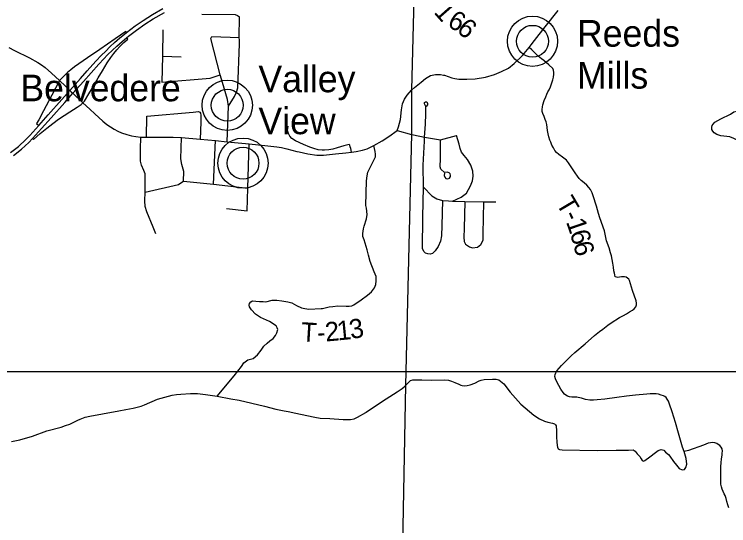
# Model space of a CAD drawing. Extents: x 2402298 to 2498138, y 789485 to 950881.
# Drawn here: x 2448638 to 2459820, y 856862 to 864863 of the extents above; entities that cross this region are included whole.
import ezdxf

# ---------------------------------------------------------------- set-up
doc = ezdxf.new("R2010")
doc.units = 0
for name, color, linetype in [('GM_X_County_Road', 7, 'Continuous'), ('GM_X_Interchange_Ramps', 7, 'Continuous'), ('GM_X_Township', 7, 'Continuous'), ('GM_X_Township_Road', 7, 'Continuous'), ('GM_X_Township_Road_Text', 7, 'Continuous'), ('GM_X_Unincorporated', 7, 'Continuous'), ('GM_X_Unincorporated_Text', 7, 'Continuous'), ('GM_X_US_Route', 7, 'Continuous'), ('SH_Text', 7, 'Continuous')]:
    doc.layers.add(name, color=color, linetype=linetype)

msp = doc.modelspace()

# ---------------------------------------------------------------- linework, layer by layer
at = {"layer": 'GM_X_County_Road'}
msp.add_line((2456697, 864345), (2456728, 864386), dxfattribs=at)
for points in [[(2456728, 864386), (2456778, 864452), (2456948, 864667), (2457153, 864924)], [(2448552, 864344), (2448641, 864299), (2448876, 864182), (2449005, 864111), (2449066, 864071), (2449119, 864030), (2449219, 863942), (2449346, 863825), (2449440, 863736), (2449509, 863672), (2449531, 863651)], [(2455372, 863908), (2455486, 863871), (2455535, 863856), (2455598, 863849), (2455720, 863848), (2455853, 863855), (2456015, 863878), (2456152, 863919), (2456262, 863966), (2456372, 864019), (2456464, 864093), (2456590, 864218), (2456697, 864345)], [(2453060, 862718), (2453095, 862709), (2453235, 862678), (2453372, 862660), (2453477, 862661), (2453574, 862667), (2453663, 862678), (2453827, 862695), (2453918, 862706), (2453987, 862714), (2454087, 862735), (2454159, 862758), (2454268, 862810), (2454394, 862884), (2454502, 862949), (2454631, 863047), (2454653, 863100), (2454682, 863219), (2454700, 863369), (2454716, 863462), (2454746, 863537), (2454785, 863598), (2454854, 863676), (2454900, 863715), (2455006, 863803), (2455074, 863860), (2455153, 863905), (2455230, 863922), (2455307, 863923), (2455356, 863913), (2455372, 863908)], [(2449531, 863651), (2449557, 863627), (2449712, 863480), (2449823, 863378), (2449901, 863305), (2450023, 863193), (2450087, 863140), (2450144, 863100), (2450201, 863066), (2450260, 863034), (2450318, 863008), (2450399, 862980), (2450474, 862961), (2450541, 862950), (2450619, 862940), (2450708, 862940), (2450982, 862943), (2451125, 862942), (2451251, 862935)], [(2451251, 862935), (2451256, 862935), (2451550, 862909), (2451785, 862886), (2451969, 862869), (2452314, 862838), (2452605, 862807), (2452745, 862791), (2452820, 862778), (2452902, 862758), (2453060, 862718)]]:
    msp.add_lwpolyline(points, dxfattribs=at)
at = {"layer": 'GM_X_Interchange_Ramps'}
for points in [[(2450392, 864576), (2450382, 864592), (2450218, 864480), (2449977, 864311), (2449785, 864180), (2449647, 864086), (2449580, 864039), (2449524, 863996), (2449473, 863953), (2449424, 863907), (2449362, 863845), (2449346, 863825)], [(2449712, 863480), (2449739, 863506), (2449805, 863618), (2449860, 863710), (2449953, 863867), (2450019, 863979), (2450094, 864105), (2450147, 864186), (2450194, 864250), (2450242, 864308), (2450290, 864359), (2450354, 864422), (2450415, 864476), (2450400, 864499)], [(2449346, 863825), (2449328, 863795), (2449282, 863707), (2449225, 863598), (2449137, 863429), (2449096, 863350), (2449021, 863210), (2448987, 863156), (2449021, 863122)], [(2448925, 862921), (2448939, 862906), (2449045, 863000), (2449147, 863084), (2449243, 863157), (2449331, 863221), (2449507, 863336), (2449623, 863412), (2449685, 863450), (2449712, 863480)]]:
    msp.add_lwpolyline(points, dxfattribs=at)
at = {"layer": 'GM_X_Township'}
msp.add_lwpolyline([(2436952, 871501), (2441170, 871455), (2443539, 871409), (2448340, 871349), (2451564, 871308), (2453075, 871274), (2455047, 871253), (2454976, 868366), (2454948, 867221), (2454912, 865985), (2454911, 865959), (2454910, 865921), (2454853, 863679), (2454854, 862987), (2454763, 859062), (2454590, 849912), (2454510, 846829), (2454470, 845007), (2454435, 843954)], dxfattribs=at)
at = {"layer": 'GM_X_Township_Road'}
for p, q in [((2451729, 864513), (2452160, 864498)), ((2456697, 864345), (2456728, 864386)), ((2450956, 864207), (2451249, 864198)), ((2451757, 862207), (2451785, 862886))]:
    msp.add_line(p, q, dxfattribs=at)
for points in [[(2456728, 864386), (2456778, 864452), (2456948, 864667), (2457153, 864924)], [(2451575, 864863), (2452096, 864857), (2452133, 864844), (2452162, 864821)], [(2452162, 864456), (2452160, 864498), (2452162, 864821)], [(2450962, 864621), (2450956, 864207), (2450949, 863803), (2451702, 863863), (2451863, 863914)], [(2451989, 863423), (2451975, 863532), (2451914, 863743), (2451863, 863914), (2451716, 864482), (2451729, 864513)], [(2451969, 862869), (2451989, 863423), (2452085, 863577), (2452117, 863643), (2452138, 863710), (2452164, 864399), (2452162, 864456)], [(2459823, 857140), (2459804, 857188), (2459788, 857240), (2459778, 857286), (2459764, 857333), (2459750, 857363), (2459733, 857399), (2459718, 857434), (2459707, 857472), (2459699, 857511), (2459695, 857564), (2459694, 857624), (2459695, 857681), (2459694, 857740), (2459695, 857789), (2459701, 857847), (2459708, 857910), (2459715, 857964), (2459718, 857998), (2459720, 858027), (2459717, 858063), (2459703, 858090), (2459683, 858116), (2459656, 858134), (2459633, 858149), (2459605, 858160), (2459571, 858164), (2459537, 858161), (2459500, 858151), (2459424, 858123), (2459350, 858094), (2459263, 858065), (2459189, 858041), (2459125, 858024), (2459098, 858090), (2459036, 858311), (2458987, 858479), (2458935, 858644), (2458895, 858764), (2458876, 858811), (2458859, 858841), (2458839, 858866), (2458822, 858883), (2458799, 858895), (2458761, 858907), (2458719, 858918), (2458683, 858923), (2458645, 858926), (2458592, 858923), (2458538, 858919), (2458362, 858902), (2458220, 858887), (2458071, 858867), (2457883, 858844), (2457759, 858829), (2457703, 858825), (2457645, 858828), (2457578, 858838), (2457518, 858855), (2457466, 858867), (2457441, 858871), (2457403, 858871), (2457364, 858872), (2457326, 858879), (2457298, 858888), (2457272, 858904), (2457251, 858922), (2457227, 858947), (2457192, 858996), (2457162, 859054), (2457124, 859121), (2457107, 859162), (2457101, 859197), (2457104, 859229), (2457114, 859255), (2457132, 859285), (2457166, 859325), (2457205, 859367), (2457265, 859432), (2457352, 859518), (2457413, 859570), (2457571, 859705), (2457720, 859836), (2457799, 859901), (2457848, 859939), (2457928, 860001), (2457979, 860037), (2458111, 860118), (2458173, 860152), (2458220, 860178), (2458268, 860206), (2458312, 860235), (2458338, 860257), (2458364, 860288), (2458376, 860317), (2458376, 860342), (2458373, 860379), (2458316, 860544), (2458267, 860697), (2458256, 860717), (2458235, 860736), (2458216, 860748), (2458190, 860755), (2458164, 860758), (2458140, 860756), (2458108, 860750), (2458083, 860747), (2458061, 860748), (2458044, 860758), (2458035, 860786), (2458030, 860812), (2458023, 860851), (2458016, 860905), (2458007, 860968), (2457986, 861082), (2457972, 861131), (2457949, 861211), (2457909, 861320), (2457874, 861473), (2457804, 861678), (2457781, 861747), (2457750, 861863), (2457699, 862023), (2457683, 862072), (2457657, 862121), (2457633, 862154), (2457601, 862190), (2457560, 862226), (2457509, 862265), (2457477, 862296), (2457453, 862329), (2457417, 862385), (2457311, 862540), (2457280, 862580), (2457221, 862629), (2457162, 862670), (2457127, 862703), (2457100, 862732), (2457075, 862774), (2457054, 862818), (2457038, 862860), (2457021, 862896), (2457006, 862944), (2456993, 862992), (2456985, 863047), (2456978, 863091), (2456972, 863137), (2456963, 863182), (2456949, 863219), (2456932, 863262), (2456911, 863309), (2456900, 863342), (2456898, 863373), (2456903, 863413), (2456910, 863447), (2456930, 863512), (2456955, 863574), (2456971, 863613), (2456991, 863649), (2457009, 863682), (2457029, 863726), (2457055, 863804), (2457065, 863838), (2457077, 863880), (2457084, 863925), (2457083, 863953), (2457077, 863990), (2457068, 864013), (2457007, 864072), (2456925, 864140), (2456892, 864166), (2456840, 864208), (2456789, 864257), (2456736, 864305), (2456697, 864345)], [(2455057, 862880), (2455060, 862942), (2455074, 863144), (2455080, 863305), (2455081, 863420), (2455068, 863440), (2455061, 863464), (2455061, 863481), (2455075, 863495), (2455094, 863493), (2455102, 863483), (2455106, 863467), (2455103, 863448), (2455087, 863420)], [(2450708, 862940), (2450713, 863270), (2451440, 863333), (2451520, 863344), (2451540, 863334), (2451555, 863316), (2451559, 863283), (2451556, 863177), (2451550, 862909)], [(2460173, 862792), (2460127, 862807), (2460074, 862823), (2460010, 862860), (2459951, 862893), (2459902, 862920), (2459839, 862945), (2459699, 862964), (2459636, 862981), (2459593, 863007), (2459571, 863032), (2459558, 863061), (2459555, 863096), (2459562, 863123), (2459575, 863145), (2459603, 863173), (2459699, 863226), (2459848, 863302), (2459901, 863335), (2459946, 863346), (2460004, 863348), (2460080, 863349), (2460285, 863343)], [(2453918, 862706), (2453906, 862765), (2453897, 862790), (2453889, 862817), (2453877, 862825), (2453858, 862820), (2453797, 862805), (2453691, 862772), (2453626, 862754), (2453563, 862743), (2453496, 862736), (2453458, 862738), (2453396, 862744), (2453328, 862761), (2453262, 862784), (2453165, 862827), (2453038, 862883), (2452984, 862918), (2452951, 862955), (2452930, 862997), (2452915, 863045), (2452926, 863114)], [(2454631, 863047), (2454855, 862984), (2454886, 862977)], [(2450855, 861426), (2450813, 861531), (2450715, 861771), (2450687, 861856), (2450680, 861947), (2450688, 862082), (2450688, 862295), (2450686, 862369), (2450665, 862420), (2450629, 862505), (2450614, 862563), (2450614, 862753), (2450619, 862940)], [(2451284, 862251), (2451293, 862403), (2451258, 862511), (2451245, 862604), (2451256, 862935)], [(2454886, 862977), (2455060, 862942), (2455307, 862897), (2455560, 862968)], [(2455044, 862161), (2455172, 862021), (2455253, 861976), (2455338, 861949), (2455433, 861943), (2455497, 861941), (2455631, 862000), (2455714, 862066), (2455778, 862179), (2455808, 862255), (2455821, 862330), (2455816, 862408), (2455785, 862501), (2455733, 862592), (2455681, 862652), (2455640, 862708), (2455616, 862765), (2455600, 862830), (2455560, 862968)], [(2455369, 862378), (2455365, 862341), (2455376, 862316), (2455395, 862295), (2455424, 862290), (2455450, 862300), (2455465, 862323), (2455465, 862348), (2455461, 862367), (2455446, 862385), (2455413, 862395), (2455372, 862388), (2455314, 862441), (2455303, 862479), (2455310, 862609), (2455307, 862897)], [(2451959, 861824), (2452284, 861790), (2452293, 862142), (2452314, 862838)], [(2453440, 860260), (2453460, 860261), (2453565, 860284), (2453624, 860294), (2453701, 860300), (2453833, 860299), (2453882, 860298), (2453919, 860303), (2453951, 860317), (2454069, 860397), (2454169, 860468), (2454229, 860522), (2454278, 860586), (2454296, 860635), (2454302, 860692), (2454300, 860759), (2454271, 860833), (2454210, 860998), (2454184, 861094), (2454159, 861176), (2454113, 861335), (2454093, 861386), (2454092, 861436), (2454103, 861506), (2454115, 861547), (2454153, 861665), (2454159, 861730), (2454151, 861829), (2454142, 861874), (2454151, 862258), (2454159, 862335), (2454171, 862395), (2454290, 862634), (2454292, 862676), (2454285, 862717), (2454268, 862810)], [(2455338, 861949), (2455330, 861560), (2455324, 861399), (2455309, 861314), (2455273, 861228), (2455228, 861160), (2455184, 861123), (2455146, 861111), (2455111, 861115), (2455072, 861128), (2455053, 861146), (2455028, 861194), (2455032, 861689), (2455044, 862161), (2455040, 862501), (2455057, 862880)], [(2450688, 862082), (2451209, 862198), (2451276, 862245)], [(2451276, 862245), (2451284, 862251), (2451757, 862207), (2452293, 862142)], [(2455497, 861941), (2455688, 861936), (2455985, 861928), (2456176, 861928)], [(2455688, 861936), (2455678, 861513), (2455675, 861376), (2455680, 861311), (2455701, 861267), (2455763, 861224), (2455810, 861208), (2455887, 861220), (2455939, 861259), (2455976, 861331), (2455978, 861426), (2455985, 861928)], [(2451811, 858887), (2452082, 859206), (2452192, 859355), (2452230, 859411), (2452292, 859455), (2452379, 859480), (2452447, 859535), (2452503, 859610), (2452543, 859669), (2452595, 859717), (2452639, 859755), (2452690, 859793), (2452727, 859838), (2452748, 859880), (2452761, 859931), (2452752, 859960), (2452738, 859991), (2452633, 860056), (2452493, 860117), (2452416, 860174), (2452350, 860237), (2452322, 860284), (2452313, 860315), (2452317, 860337), (2452340, 860366), (2452367, 860378), (2452417, 860377), (2452477, 860372), (2452536, 860369), (2452574, 860367), (2452674, 860389), (2452746, 860391), (2452826, 860381), (2452920, 860366), (2452980, 860348), (2453054, 860308), (2453136, 860273), (2453183, 860258), (2453249, 860249), (2453440, 860260)], [(2454147, 858638), (2454403, 858809), (2454632, 858958), (2454710, 859008), (2454740, 859035), (2454764, 859059), (2454831, 859121)], [(2454831, 859121), (2454842, 859132), (2454874, 859144), (2455019, 859144), (2455174, 859140), (2455368, 859146), (2455435, 859138), (2455480, 859125), (2455535, 859102), (2455596, 859074), (2455625, 859062), (2455649, 859056), (2455683, 859052), (2455724, 859054), (2455773, 859065), (2455845, 859091), (2455912, 859128), (2455948, 859141), (2455993, 859149), (2456125, 859154), (2456179, 859156), (2456220, 859145), (2456300, 859081), (2456400, 858954), (2456568, 858763), (2456768, 858591), (2456861, 858535), (2456937, 858497), (2456990, 858481), (2457062, 858468), (2457095, 858455), (2457111, 858442), (2457121, 858423), (2457126, 858344), (2457127, 858245), (2457128, 858173), (2457136, 858117), (2457141, 858089), (2457153, 858067), (2457170, 858053), (2457214, 858049), (2457762, 858038), (2458057, 858045), (2458251, 858046), (2458324, 858048), (2458358, 858027), (2458389, 857989), (2458428, 857947), (2458450, 857910), (2458463, 857882), (2458487, 857874), (2458509, 857883), (2458585, 857938), (2458675, 858008), (2458714, 858041), (2458763, 858056), (2458806, 858042), (2458833, 858015), (2458877, 857975), (2458896, 857949)], [(2448592, 858180), (2448724, 858208), (2448924, 858264), (2449145, 858344), (2449372, 858405), (2449442, 858430), (2449507, 858453), (2449633, 858511), (2449671, 858529), (2449749, 858559), (2449818, 858576), (2450018, 858614), (2450275, 858661), (2450384, 858679), (2450499, 858702), (2450559, 858717), (2450622, 858733), (2450677, 858751), (2450879, 858841), (2451108, 858903), (2451178, 858913), (2451245, 858922), (2451394, 858929), (2451508, 858929), (2451629, 858917), (2451811, 858887), (2452027, 858845), (2452156, 858824), (2452357, 858778), (2452555, 858733), (2452734, 858688), (2452786, 858673), (2452860, 858662), (2452926, 858650), (2453043, 858625), (2453216, 858589), (2453341, 858560), (2453424, 858547), (2453577, 858541), (2453787, 858523), (2453899, 858523), (2453958, 858535), (2454011, 858560), (2454142, 858635), (2454147, 858638)], [(2458896, 857949), (2458954, 857869), (2459003, 857810), (2459045, 857757), (2459092, 857736), (2459128, 857740), (2459147, 857771), (2459162, 857823), (2459156, 857912), (2459125, 858024)]]:
    msp.add_lwpolyline(points, dxfattribs=at)
at = {"layer": 'GM_X_Unincorporated'}
for centre, radius in [((2456749, 864441), 393), ((2456749, 864441), 249), ((2451971, 863440), 393), ((2451971, 863440), 249), ((2452218, 862534), 393), ((2452218, 862534), 249)]:
    msp.add_circle(centre, radius, dxfattribs=at)
at = {"layer": 'GM_X_US_Route'}
for points in [[(2448580, 862701), (2448703, 862797), (2448820, 862905), (2448879, 862966), (2449021, 863122), (2449169, 863289), (2449382, 863528), (2449509, 863672), (2449674, 863857), (2449780, 863976), (2449915, 864127), (2450003, 864222), (2450064, 864282), (2450141, 864358), (2450207, 864419), (2450292, 864493), (2450365, 864554), (2450392, 864576), (2450532, 864681), (2450654, 864766), (2450800, 864859), (2450963, 864952)], [(2448626, 862655), (2448749, 862752), (2448865, 862859), (2448925, 862921), (2449066, 863077), (2449215, 863244), (2449429, 863484), (2449557, 863627), (2449719, 863811), (2449960, 864081), (2450038, 864167), (2450098, 864227), (2450176, 864303), (2450242, 864364), (2450326, 864438), (2450400, 864499), (2450426, 864521), (2450549, 864614), (2450680, 864707), (2450814, 864793), (2450987, 864893)]]:
    msp.add_lwpolyline(points, dxfattribs=at)
at = {"layer": 'SH_Text'}
msp.add_lwpolyline([(2448187, 889729), (2496836, 889729), (2496836, 859271), (2448187, 859271)], close=True, dxfattribs=at)

# ---------------------------------------------------------------- texts
at = {"layer": 'GM_X_Township_Road_Text'}
for s, rotation, p in [('1', 311.325, (2455193, 864891)), ('6', 330.4356, (2455399, 864685)), ('6', 319.7008, (2455546, 864603)), ('T', 300.6411, (2457110, 861907)), ('1', 288.9698, (2457271, 861618)), ('-', 295.5597, (2457221, 861721)), ('6', 286.603, (2457330, 861446)), ('6', 285.2291, (2457382, 861271)), ('3', 9.7759, (2453908, 859781)), ('T', 356.475, (2453118, 859748)), ('2', 5.1125, (2453514, 859743)), ('1', 5.6037, (2453701, 859760)), ('-', 3.9965, (2453385, 859734))]:
    msp.add_text(s, height=300, rotation=rotation, dxfattribs=at).set_placement(p)
at = {"layer": 'GM_X_Unincorporated_Text'}
for s, p in [('Reeds', (2457445, 864356)), ('Mills', (2457445, 863700)), ('Valley', (2452459, 863643)), ('Belvedere', (2448733, 863502)), ('View', (2452459, 862987))]:
    msp.add_text(s, height=417, rotation=0, dxfattribs=at).set_placement(p)

doc.saveas('drawing.dxf')
